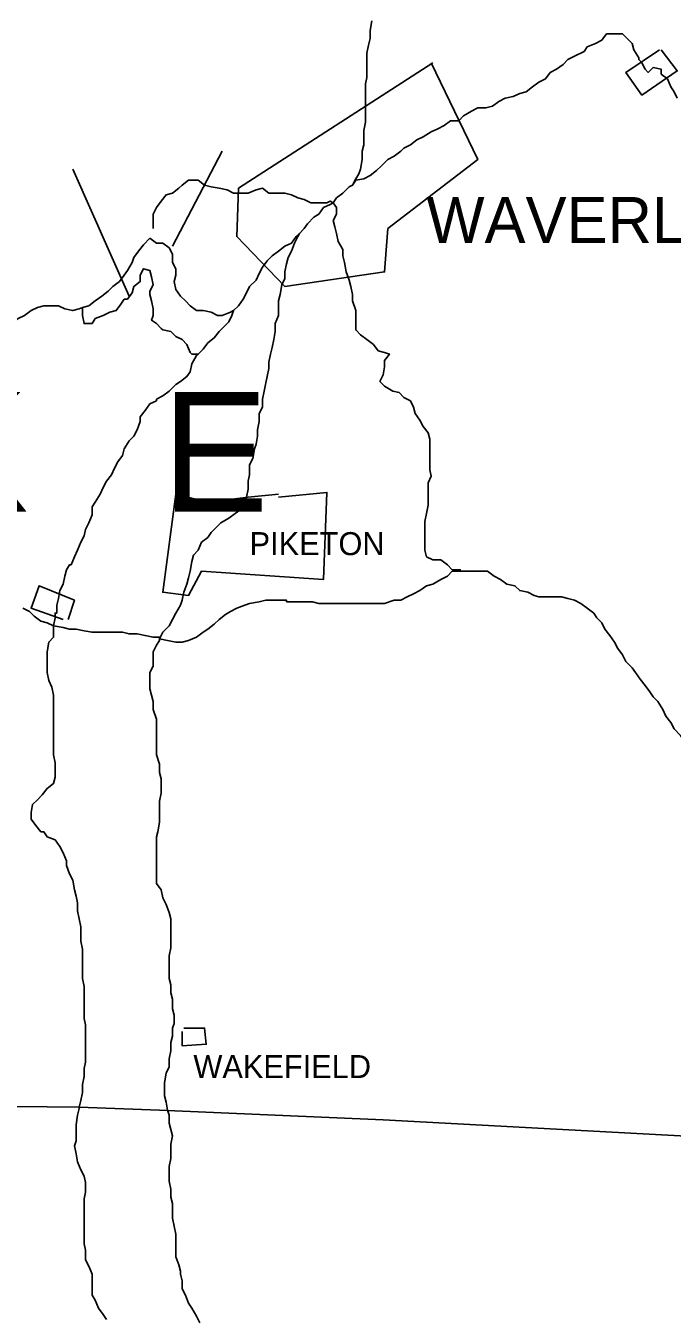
# Model space of a CAD drawing. Extents: x 0 to 40.2, y 0 to 22.
# Drawn here: x 5.818 to 6.366, y 17.238 to 18.331 of the extents above; entities that cross this region are included whole.
import ezdxf

# ---------------------------------------------------------------- set-up
doc = ezdxf.new("R2010")
doc.units = 0
doc.layers.add('Default', color=7, linetype='Continuous')
doc.layers.add('TR_Turning_Path1', color=7, linetype='Continuous')

msp = doc.modelspace()

# ---------------------------------------------------------------- linework, layer by layer
at = {"layer": 'Default'}
for p, q in [((5.9843, 18.2246), (5.9421, 18.1442)), ((5.8575, 18.2096), (5.9053, 18.1019))]:
    msp.add_line(p, q, dxfattribs=at)
for points in [[(6.0948, 18.196), (6.0975, 18.2014), (6.1002, 18.2055), (6.1016, 18.2096), (6.103, 18.2178), (6.103, 18.2246), (6.1043, 18.2301), (6.1043, 18.2369), (6.1043, 18.2423), (6.1057, 18.2492), (6.1057, 18.256), (6.1057, 18.2614), (6.1057, 18.2696), (6.1057, 18.2751), (6.1057, 18.2819), (6.107, 18.2873), (6.107, 18.2942), (6.107, 18.2996), (6.107, 18.3078), (6.1084, 18.3146), (6.1098, 18.3201), (6.1098, 18.3269), (6.1111, 18.3351)], [(6.0948, 18.196), (6.0975, 18.2014), (6.1002, 18.2055), (6.1016, 18.2096), (6.103, 18.2178), (6.103, 18.2246), (6.1043, 18.2301), (6.1043, 18.2369), (6.1043, 18.2423), (6.1057, 18.2492), (6.1057, 18.256), (6.1057, 18.2614), (6.1057, 18.2696), (6.1057, 18.2751), (6.1057, 18.2819), (6.107, 18.2873), (6.107, 18.2942), (6.107, 18.2996), (6.107, 18.3078), (6.1084, 18.3146), (6.1098, 18.3201), (6.1098, 18.3269), (6.1111, 18.3351)], [(6.3375, 18.3037), (6.3334, 18.3105), (6.332, 18.316), (6.3266, 18.3214), (6.3238, 18.3241), (6.317, 18.3241), (6.3102, 18.3241), (6.3061, 18.3187), (6.3007, 18.316), (6.2938, 18.3132), (6.2911, 18.3092), (6.2829, 18.3051), (6.2775, 18.3023), (6.2734, 18.2982), (6.2679, 18.2942), (6.2625, 18.2914), (6.2584, 18.286), (6.2529, 18.2832), (6.2475, 18.2792), (6.242, 18.2751), (6.2366, 18.2737), (6.2311, 18.271), (6.2243, 18.2696), (6.2188, 18.2669), (6.2134, 18.2628), (6.2079, 18.2614), (6.2011, 18.2614), (6.1957, 18.2587), (6.1889, 18.2546), (6.1848, 18.2505), (6.1779, 18.2505), (6.1725, 18.2464), (6.167, 18.2437), (6.1616, 18.241), (6.1548, 18.2369), (6.1493, 18.2342), (6.1439, 18.2301), (6.1384, 18.2273), (6.1357, 18.2246), (6.1302, 18.2205), (6.1248, 18.2178), (6.1193, 18.2123), (6.1152, 18.2083), (6.1098, 18.2042), (6.1043, 18.2014), (6.0975, 18.2001), (6.0948, 18.196), (6.0948, 18.196), (6.0948, 18.196)], [(6.3552, 18.3105), (6.3266, 18.2914), (6.3402, 18.2723), (6.3702, 18.2928), (6.3566, 18.3105)], [(6.1629, 18.2996), (5.998, 18.1933), (5.9966, 18.1524), (6.0375, 18.1101), (6.122, 18.1224), (6.1248, 18.1592), (6.2011, 18.2178), (6.1616, 18.2996)], [(6.3702, 18.2696), (6.3675, 18.2751), (6.3647, 18.2792), (6.362, 18.286), (6.3566, 18.2901), (6.3566, 18.2942), (6.3497, 18.2955), (6.3456, 18.2914), (6.3429, 18.2942), (6.3402, 18.2996), (6.3375, 18.3023), (6.3375, 18.3037)], [(5.9257, 18.1592), (5.9257, 18.1646), (5.9257, 18.1714), (5.9284, 18.1769), (5.9325, 18.1824), (5.9366, 18.1878), (5.9421, 18.1892), (5.9475, 18.1933), (5.9503, 18.196), (5.9557, 18.2001), (5.9598, 18.2001), (5.9639, 18.2001), (5.9639, 18.2001)], [(5.9639, 18.2001), (5.9693, 18.196), (5.9748, 18.1946), (5.9816, 18.1933), (5.9884, 18.1919), (5.9939, 18.1892), (5.9993, 18.1892), (6.0062, 18.1892), (6.013, 18.1919), (6.0184, 18.1933), (6.0239, 18.1892), (6.0293, 18.1892), (6.0375, 18.1892), (6.043, 18.1878), (6.0484, 18.1851), (6.0539, 18.1837), (6.0593, 18.181), (6.0648, 18.181), (6.073, 18.181), (6.0757, 18.1824), (6.0784, 18.181)], [(6.0784, 18.181), (6.0811, 18.1851), (6.0866, 18.1892), (6.092, 18.1946), (6.0948, 18.196), (6.0948, 18.196)], [(6.0784, 18.181), (6.0811, 18.1851), (6.0866, 18.1892), (6.092, 18.1946), (6.0948, 18.196), (6.0948, 18.196)], [(6.0498, 18.1551), (6.0539, 18.1592), (6.0566, 18.1633), (6.0621, 18.1687), (6.0661, 18.1714), (6.0702, 18.1769), (6.0757, 18.1796), (6.0784, 18.181)], [(6.0498, 18.1551), (6.0539, 18.1592), (6.0566, 18.1633), (6.0621, 18.1687), (6.0661, 18.1714), (6.0702, 18.1769), (6.0757, 18.1796), (6.0784, 18.181)], [(6.0784, 18.181), (6.0811, 18.1769), (6.0811, 18.1714), (6.0784, 18.166), (6.0798, 18.1605), (6.0811, 18.1551), (6.0825, 18.1483), (6.0866, 18.1414), (6.0866, 18.136), (6.088, 18.1305), (6.0893, 18.1224), (6.0893, 18.1224)], [(5.9939, 18.0896), (5.998, 18.0937), (6.0021, 18.0992), (6.0048, 18.1046), (6.0075, 18.1101), (6.013, 18.1155), (6.0157, 18.121), (6.0184, 18.1265), (6.0225, 18.1319), (6.0266, 18.136), (6.0321, 18.1401), (6.0375, 18.1442), (6.043, 18.1469), (6.0471, 18.1524), (6.0498, 18.1551)], [(6.0143, 17.9887), (6.0157, 17.9956), (6.0157, 18.0024), (6.0184, 18.0078), (6.0184, 18.0147), (6.0198, 18.0215), (6.0212, 18.0283), (6.0225, 18.0337), (6.0239, 18.0406), (6.0239, 18.046), (6.0252, 18.0528), (6.0266, 18.0583), (6.028, 18.0651), (6.0293, 18.0719), (6.0293, 18.0787), (6.0321, 18.0855), (6.0321, 18.091), (6.0321, 18.0978), (6.0334, 18.1033), (6.0348, 18.1115), (6.0375, 18.1169), (6.0375, 18.1224), (6.0389, 18.1292), (6.0402, 18.1346), (6.043, 18.1401), (6.0457, 18.1469), (6.0484, 18.1524), (6.0498, 18.1551)], [(5.8657, 18.0924), (5.8712, 18.0937), (5.8766, 18.0978), (5.8821, 18.1019), (5.8875, 18.106), (5.8916, 18.1101), (5.8971, 18.1142), (5.9012, 18.1196), (5.9039, 18.1237), (5.908, 18.1305), (5.9094, 18.1346), (5.9134, 18.1401), (5.9175, 18.1455), (5.923, 18.151), (5.923, 18.151)], [(5.923, 18.151), (5.9284, 18.1469), (5.9339, 18.1469), (5.9393, 18.1428), (5.9421, 18.1374), (5.9421, 18.1305), (5.9448, 18.1251), (5.9448, 18.1196), (5.9434, 18.1142), (5.9448, 18.1074), (5.9489, 18.1019), (5.953, 18.0978), (5.9571, 18.0937), (5.9625, 18.0896), (5.968, 18.0896), (5.9748, 18.0883), (5.9802, 18.0855), (5.9843, 18.0855), (5.9912, 18.0883), (5.9939, 18.0896), (5.9939, 18.0896)], [(5.9039, 18.0992), (5.908, 18.1046), (5.9094, 18.1101), (5.9148, 18.1142), (5.9148, 18.1196), (5.9175, 18.1251), (5.923, 18.1237), (5.9243, 18.1183), (5.9257, 18.1115), (5.923, 18.106), (5.923, 18.1046), (5.923, 18.1033)], [(6.0893, 18.1224), (6.092, 18.1155), (6.0934, 18.1101), (6.0948, 18.1033), (6.0948, 18.0978), (6.0975, 18.0896), (6.0975, 18.0855), (6.0975, 18.0787), (6.0975, 18.0733), (6.1016, 18.0692), (6.107, 18.0651), (6.1125, 18.061), (6.1166, 18.0556), (6.122, 18.0542), (6.1261, 18.0528), (6.122, 18.0474), (6.122, 18.0419), (6.1207, 18.0351), (6.118, 18.0296), (6.118, 18.0296), (6.118, 18.0296)], [(5.8657, 18.0924), (5.8657, 18.0855), (5.8671, 18.0787), (5.8739, 18.0787), (5.8766, 18.0828), (5.8834, 18.0855), (5.8889, 18.0883), (5.8944, 18.0896), (5.8984, 18.0951), (5.9012, 18.0992), (5.9039, 18.0992)], [(5.923, 18.1033), (5.9243, 18.0978), (5.9257, 18.091), (5.9257, 18.0855), (5.9243, 18.0815), (5.9284, 18.0787), (5.9325, 18.0746), (5.9339, 18.0733), (5.9339, 18.0733)], [(5.8057, 18.0787), (5.8112, 18.0828), (5.8166, 18.0855), (5.8221, 18.0896), (5.8275, 18.0924), (5.833, 18.0937), (5.8398, 18.0937), (5.8453, 18.0937), (5.8507, 18.091), (5.8575, 18.0896), (5.863, 18.091), (5.8657, 18.0924)], [(5.9639, 18.0528), (5.968, 18.0569), (5.9721, 18.0624), (5.9775, 18.0665), (5.9816, 18.0719), (5.9857, 18.076), (5.9898, 18.0801), (5.9925, 18.0855), (5.9939, 18.0896)], [(5.9339, 18.0733), (5.9407, 18.0719), (5.9448, 18.0678), (5.9503, 18.0651), (5.9543, 18.061), (5.9571, 18.0542), (5.9584, 18.0528), (5.9639, 18.0528), (5.9639, 18.0528)], [(5.9284, 18.0147), (5.9339, 18.0174), (5.9393, 18.0215), (5.9448, 18.0269), (5.9489, 18.0296), (5.9543, 18.0337), (5.9571, 18.0378), (5.9584, 18.0446), (5.9625, 18.0515), (5.9639, 18.0528)], [(6.118, 18.0296), (6.122, 18.0256), (6.1289, 18.0215), (6.1343, 18.0201), (6.1384, 18.016), (6.1439, 18.0133), (6.1466, 18.0078), (6.148, 18.0024), (6.152, 17.9969), (6.1548, 17.9915), (6.1589, 17.986), (6.1602, 17.9806), (6.1602, 17.9737), (6.1602, 17.9669), (6.1602, 17.9615), (6.1602, 17.9547), (6.1616, 17.9492)], [(5.8562, 17.8742), (5.8589, 17.881), (5.8616, 17.8865), (5.8644, 17.8933), (5.8671, 17.8988), (5.8684, 17.9042), (5.8712, 17.9097), (5.8739, 17.9165), (5.8739, 17.9233), (5.8766, 17.9274), (5.8807, 17.9342), (5.8834, 17.9397), (5.8862, 17.9451), (5.8903, 17.9506), (5.893, 17.956), (5.8957, 17.9615), (5.8998, 17.9669), (5.9012, 17.9724), (5.9053, 17.9792), (5.9094, 17.9833), (5.9121, 17.9887), (5.9148, 17.9956), (5.9148, 17.9997), (5.9189, 18.0051), (5.923, 18.0106), (5.9284, 18.0133), (5.9284, 18.0147)], [(5.9312, 17.8115), (5.9339, 17.817), (5.9393, 17.8224), (5.9421, 17.8279), (5.9448, 17.8333), (5.9489, 17.8401), (5.9503, 17.8442), (5.9516, 17.851), (5.9543, 17.8579), (5.9557, 17.8633), (5.9571, 17.8688), (5.9584, 17.8769), (5.9598, 17.8824), (5.9639, 17.8865), (5.9666, 17.8933), (5.9721, 17.8974), (5.9748, 17.9015), (5.9802, 17.9069), (5.983, 17.9097), (5.9898, 17.9138), (5.9952, 17.9178), (5.9993, 17.9206), (6.0034, 17.926), (6.0048, 17.9315), (6.0062, 17.9383), (6.0062, 17.9451), (6.0075, 17.9506), (6.0075, 17.9588), (6.0102, 17.9642), (6.0116, 17.9724), (6.013, 17.9765), (6.0143, 17.9833), (6.0143, 17.9874), (6.0143, 17.9887)], [(6.1616, 17.9492), (6.1589, 17.9438), (6.1589, 17.9383), (6.1589, 17.9315), (6.1589, 17.9247), (6.1575, 17.9178), (6.1561, 17.911), (6.1561, 17.9056), (6.1561, 17.8988), (6.1561, 17.8933), (6.1561, 17.8865), (6.1575, 17.881), (6.1629, 17.8783), (6.1698, 17.8783), (6.1752, 17.8742), (6.1793, 17.8701), (6.1861, 17.8701), (6.1861, 17.8688)], [(6.0321, 17.9315), (6.073, 17.9356), (6.0702, 17.8619), (5.9666, 17.8688), (5.9557, 17.8483), (5.9339, 17.851), (5.9448, 17.9342), (5.9721, 17.9274), (6.0062, 17.9315), (6.0321, 17.9342)], [(5.8439, 17.8333), (5.8439, 17.8401), (5.8453, 17.8456), (5.8466, 17.8524), (5.8494, 17.8579), (5.8507, 17.8647), (5.8521, 17.8701), (5.8548, 17.8742), (5.8562, 17.8742)], [(6.0389, 17.8429), (6.0457, 17.8429), (6.0539, 17.8429), (6.0607, 17.8429), (6.0661, 17.8415), (6.073, 17.8415), (6.0798, 17.8415), (6.0866, 17.8415), (6.092, 17.8415), (6.0975, 17.8415), (6.1057, 17.8415), (6.1111, 17.8415), (6.118, 17.8415), (6.122, 17.8415), (6.1302, 17.8442), (6.1357, 17.8442), (6.1411, 17.847), (6.1466, 17.8497), (6.152, 17.8524), (6.1575, 17.8565), (6.1629, 17.8579), (6.1698, 17.8619), (6.1752, 17.8647), (6.1793, 17.8688), (6.1848, 17.8688), (6.1861, 17.8688)], [(6.0389, 17.8429), (6.0457, 17.8429), (6.0539, 17.8429), (6.0607, 17.8429), (6.0661, 17.8415), (6.073, 17.8415), (6.0798, 17.8415), (6.0866, 17.8415), (6.092, 17.8415), (6.0975, 17.8415), (6.1057, 17.8415), (6.1111, 17.8415), (6.118, 17.8415), (6.122, 17.8415), (6.1302, 17.8442), (6.1357, 17.8442), (6.1411, 17.847), (6.1466, 17.8497), (6.152, 17.8524), (6.1575, 17.8565), (6.1629, 17.8579), (6.1698, 17.8619), (6.1752, 17.8647), (6.1793, 17.8688), (6.1848, 17.8688), (6.1861, 17.8688)], [(6.1861, 17.8688), (6.1929, 17.8688), (6.1984, 17.8688), (6.2039, 17.8688), (6.2093, 17.8688), (6.2148, 17.8647), (6.2202, 17.8619), (6.2257, 17.8579), (6.2325, 17.8565), (6.2366, 17.8524), (6.2434, 17.851), (6.2488, 17.8483), (6.2529, 17.847), (6.2598, 17.847), (6.2666, 17.847), (6.272, 17.847), (6.2775, 17.8456), (6.2829, 17.8442), (6.2884, 17.8415), (6.2884, 17.8415)], [(6.1861, 17.8688), (6.1929, 17.8688), (6.1984, 17.8688), (6.2039, 17.8688), (6.2093, 17.8688), (6.2148, 17.8647), (6.2202, 17.8619), (6.2257, 17.8579), (6.2325, 17.8565), (6.2366, 17.8524), (6.2434, 17.851), (6.2488, 17.8483), (6.2529, 17.847), (6.2598, 17.847), (6.2666, 17.847), (6.272, 17.847), (6.2775, 17.8456), (6.2829, 17.8442), (6.2884, 17.8415), (6.2884, 17.8415)], [(5.8494, 17.8279), (5.8221, 17.8374), (5.8289, 17.8565), (5.8589, 17.8442), (5.8535, 17.8279)], [(5.8153, 17.8374), (5.8207, 17.8347), (5.8248, 17.8306), (5.8303, 17.8265), (5.8357, 17.8251), (5.8412, 17.8224), (5.8412, 17.8224), (5.8412, 17.8224)], [(5.8153, 17.8374), (5.8207, 17.8347), (5.8248, 17.8306), (5.8303, 17.8265), (5.8357, 17.8251), (5.8412, 17.8224), (5.8412, 17.8224), (5.8412, 17.8224)], [(5.9312, 17.8115), (5.938, 17.8101), (5.9448, 17.8088), (5.9503, 17.8088), (5.9557, 17.8101), (5.9625, 17.8129), (5.968, 17.817), (5.9721, 17.8197), (5.9775, 17.8238), (5.9816, 17.8279), (5.9871, 17.832), (5.9912, 17.8347), (5.9966, 17.8374), (6.0034, 17.8401), (6.0075, 17.8415), (6.0157, 17.8429), (6.0212, 17.8442), (6.028, 17.8442), (6.0334, 17.8442), (6.0389, 17.8442), (6.0389, 17.8429)], [(5.9312, 17.8115), (5.938, 17.8101), (5.9448, 17.8088), (5.9503, 17.8088), (5.9557, 17.8101), (5.9625, 17.8129), (5.968, 17.817), (5.9721, 17.8197), (5.9775, 17.8238), (5.9816, 17.8279), (5.9871, 17.832), (5.9912, 17.8347), (5.9966, 17.8374), (6.0034, 17.8401), (6.0075, 17.8415), (6.0157, 17.8429), (6.0212, 17.8442), (6.028, 17.8442), (6.0334, 17.8442), (6.0389, 17.8442), (6.0389, 17.8429)], [(6.2884, 17.8415), (6.2938, 17.8374), (6.2993, 17.8333), (6.302, 17.8292), (6.3061, 17.8251), (6.3088, 17.8197), (6.3129, 17.8142), (6.317, 17.8088), (6.3197, 17.8033), (6.3238, 17.7979), (6.3266, 17.7924), (6.332, 17.787), (6.3347, 17.7829), (6.3388, 17.7774), (6.3429, 17.772), (6.347, 17.7665), (6.3497, 17.7624), (6.3538, 17.7583), (6.3538, 17.7583)], [(6.2884, 17.8415), (6.2938, 17.8374), (6.2993, 17.8333), (6.302, 17.8292), (6.3061, 17.8251), (6.3088, 17.8197), (6.3129, 17.8142), (6.317, 17.8088), (6.3197, 17.8033), (6.3238, 17.7979), (6.3266, 17.7924), (6.332, 17.787), (6.3347, 17.7829), (6.3388, 17.7774), (6.3429, 17.772), (6.347, 17.7665), (6.3497, 17.7624), (6.3538, 17.7583), (6.3538, 17.7583)], [(5.8412, 17.8224), (5.8425, 17.8292), (5.8425, 17.8333), (5.8439, 17.8333)], [(5.8303, 17.6479), (5.8262, 17.6533), (5.8221, 17.6588), (5.8221, 17.6643), (5.8235, 17.6711), (5.8275, 17.6752), (5.8316, 17.6792), (5.8357, 17.6847), (5.8412, 17.6888), (5.8425, 17.6942), (5.8425, 17.6997), (5.8425, 17.7065), (5.8412, 17.7133), (5.8412, 17.7202), (5.8412, 17.727), (5.8412, 17.7324), (5.8412, 17.7392), (5.8412, 17.7447), (5.8412, 17.7515), (5.8412, 17.7583), (5.8412, 17.7638), (5.8398, 17.7706), (5.8371, 17.7761), (5.8357, 17.7829), (5.8357, 17.7883), (5.8357, 17.7951), (5.8357, 17.8006), (5.8371, 17.8088), (5.8412, 17.8129), (5.8412, 17.8197), (5.8412, 17.821), (5.8412, 17.8224)], [(5.8412, 17.8224), (5.8494, 17.821), (5.8548, 17.8197), (5.8603, 17.8197), (5.8671, 17.8183), (5.8739, 17.817), (5.8794, 17.817), (5.8862, 17.817), (5.893, 17.817), (5.8998, 17.817), (5.9053, 17.8156), (5.9121, 17.8156), (5.9189, 17.8142), (5.9257, 17.8129), (5.9312, 17.8129), (5.9312, 17.8115)], [(5.8412, 17.8224), (5.8494, 17.821), (5.8548, 17.8197), (5.8603, 17.8197), (5.8671, 17.8183), (5.8739, 17.817), (5.8794, 17.817), (5.8862, 17.817), (5.893, 17.817), (5.8998, 17.817), (5.9053, 17.8156), (5.9121, 17.8156), (5.9189, 17.8142), (5.9257, 17.8129), (5.9312, 17.8129), (5.9312, 17.8115)], [(5.9312, 17.6683), (5.9312, 17.6738), (5.9325, 17.6806), (5.9325, 17.6874), (5.9325, 17.6929), (5.9312, 17.6983), (5.9312, 17.7052), (5.9284, 17.7133), (5.9284, 17.7188), (5.9284, 17.7256), (5.9284, 17.7311), (5.9284, 17.7379), (5.9284, 17.7433), (5.9257, 17.7515), (5.9257, 17.7583), (5.9243, 17.7638), (5.923, 17.7692), (5.923, 17.7761), (5.923, 17.7829), (5.9257, 17.7883), (5.9257, 17.7951), (5.9257, 17.8006), (5.9284, 17.806), (5.9312, 17.8101), (5.9312, 17.8115)], [(6.3538, 17.7583), (6.3579, 17.7515), (6.3606, 17.7461), (6.3647, 17.7406), (6.3675, 17.7352), (6.3729, 17.7297), (6.3756, 17.7256), (6.3797, 17.7215), (6.3838, 17.7147), (6.3879, 17.7106), (6.392, 17.7052), (6.3988, 17.7024), (6.4043, 17.6997), (6.4097, 17.6983), (6.4165, 17.697), (6.422, 17.697), (6.4288, 17.6956), (6.4356, 17.6942), (6.4411, 17.6942), (6.4479, 17.6942), (6.4493, 17.6942)], [(6.3538, 17.7583), (6.3579, 17.7515), (6.3606, 17.7461), (6.3647, 17.7406), (6.3675, 17.7352), (6.3729, 17.7297), (6.3756, 17.7256), (6.3797, 17.7215), (6.3838, 17.7147), (6.3879, 17.7106), (6.392, 17.7052), (6.3988, 17.7024), (6.4043, 17.6997), (6.4097, 17.6983), (6.4165, 17.697), (6.422, 17.697), (6.4288, 17.6956), (6.4356, 17.6942), (6.4411, 17.6942), (6.4479, 17.6942), (6.4493, 17.6942)], [(5.938, 17.412), (5.9366, 17.4188), (5.9353, 17.4243), (5.9353, 17.4311), (5.9353, 17.4352), (5.9366, 17.4434), (5.9393, 17.4488), (5.9393, 17.4556), (5.9407, 17.4625), (5.9407, 17.4693), (5.9421, 17.4747), (5.9421, 17.4816), (5.9434, 17.4856), (5.9434, 17.4925), (5.9421, 17.4979), (5.9421, 17.5061), (5.9407, 17.5115), (5.9407, 17.5184), (5.9393, 17.5238), (5.9393, 17.5306), (5.9393, 17.5375), (5.9393, 17.5429), (5.9407, 17.5497), (5.9407, 17.5552), (5.9407, 17.562), (5.9407, 17.5674), (5.9407, 17.5743), (5.9393, 17.5797), (5.9366, 17.5865), (5.9339, 17.592), (5.9325, 17.5988), (5.9284, 17.6043), (5.9284, 17.6111), (5.9284, 17.6165), (5.9284, 17.6233), (5.9284, 17.6302), (5.9284, 17.637), (5.9284, 17.6438), (5.9298, 17.6479), (5.9312, 17.6561), (5.9312, 17.6615), (5.9312, 17.667), (5.9312, 17.667), (5.9312, 17.6683)], [(5.863, 17.4147), (5.8644, 17.4202), (5.8657, 17.427), (5.8657, 17.4338), (5.8671, 17.4407), (5.8671, 17.4475), (5.8684, 17.4529), (5.8684, 17.4584), (5.8684, 17.4666), (5.8684, 17.472), (5.8684, 17.4775), (5.8684, 17.4843), (5.8671, 17.4897), (5.8671, 17.4979), (5.8671, 17.5034), (5.8671, 17.5102), (5.8671, 17.517), (5.8657, 17.5238), (5.8657, 17.5293), (5.8657, 17.5347), (5.8657, 17.5415), (5.8657, 17.5484), (5.8644, 17.5552), (5.8644, 17.562), (5.8644, 17.5674), (5.863, 17.5743), (5.8616, 17.5811), (5.8616, 17.5879), (5.8603, 17.5934), (5.8589, 17.5988), (5.8575, 17.607), (5.8548, 17.6124), (5.8521, 17.6193), (5.8521, 17.6233), (5.8494, 17.6302), (5.8466, 17.6356), (5.8425, 17.6411), (5.8357, 17.6438), (5.833, 17.6479), (5.8316, 17.6479), (5.8303, 17.6479)], [(5.9503, 17.4788), (5.9503, 17.4666), (5.9707, 17.4679), (5.9693, 17.4816), (5.9516, 17.4816)], [(5.2754, 17.4311), (5.4172, 17.4243), (5.5399, 17.4202), (5.7267, 17.4161), (5.863, 17.4147), (5.9312, 17.412), (6.1207, 17.4038), (6.3988, 17.3888), (6.5093, 17.382), (6.6688, 17.3711), (6.7029, 17.3684)], [(5.8739, 17.2607), (5.8739, 17.2675), (5.8739, 17.273), (5.8712, 17.2798), (5.8684, 17.2852), (5.8684, 17.2934), (5.8671, 17.2989), (5.8671, 17.3057), (5.8671, 17.3125), (5.8671, 17.3179), (5.8671, 17.3248), (5.8671, 17.3302), (5.8671, 17.337), (5.8684, 17.3425), (5.8684, 17.3507), (5.8671, 17.3561), (5.8644, 17.3616), (5.8616, 17.3684), (5.8603, 17.3752), (5.8589, 17.382), (5.8603, 17.3861), (5.8603, 17.3929), (5.8603, 17.3997), (5.8616, 17.4079), (5.863, 17.4134), (5.863, 17.4147)], [(5.9489, 17.2757), (5.9475, 17.2811), (5.9448, 17.2879), (5.9448, 17.2934), (5.9448, 17.3016), (5.9448, 17.307), (5.9434, 17.3139), (5.9421, 17.3207), (5.9421, 17.3261), (5.9421, 17.3329), (5.9407, 17.3384), (5.9407, 17.3452), (5.9393, 17.352), (5.9393, 17.3588), (5.9393, 17.3643), (5.9407, 17.3711), (5.9407, 17.3766), (5.9407, 17.3834), (5.9421, 17.3902), (5.9407, 17.3957), (5.9393, 17.4011), (5.9393, 17.4079), (5.938, 17.412), (5.938, 17.412)], [(5.9653, 17.232), (5.9625, 17.2375), (5.9584, 17.2443), (5.9557, 17.2484), (5.953, 17.2552), (5.9503, 17.2607), (5.9503, 17.2675), (5.9489, 17.273), (5.9489, 17.2743), (5.9489, 17.2757)], [(5.8862, 17.2348), (5.8834, 17.2389), (5.8794, 17.2443), (5.8766, 17.2511), (5.8739, 17.2552), (5.8739, 17.2607), (5.8739, 17.2607)]]:
    msp.add_lwpolyline(points, dxfattribs=at)

# ---------------------------------------------------------------- texts
for s, height, p in [('WAVERLY', 0.039, (6.1575, 18.1469)), ('PIKETON', 0.0195, (6.0075, 17.8824)), ('WAKEFIELD', 0.0195, (5.9598, 17.4393))]:
    msp.add_text(s, height=height, dxfattribs=at).set_placement(p)
at = {"layer": 'TR_Turning_Path1'}
msp.add_text('P   I   K   E', height=0.101489, dxfattribs=at).set_placement((5.3749, 17.9192))

doc.saveas('drawing.dxf')
